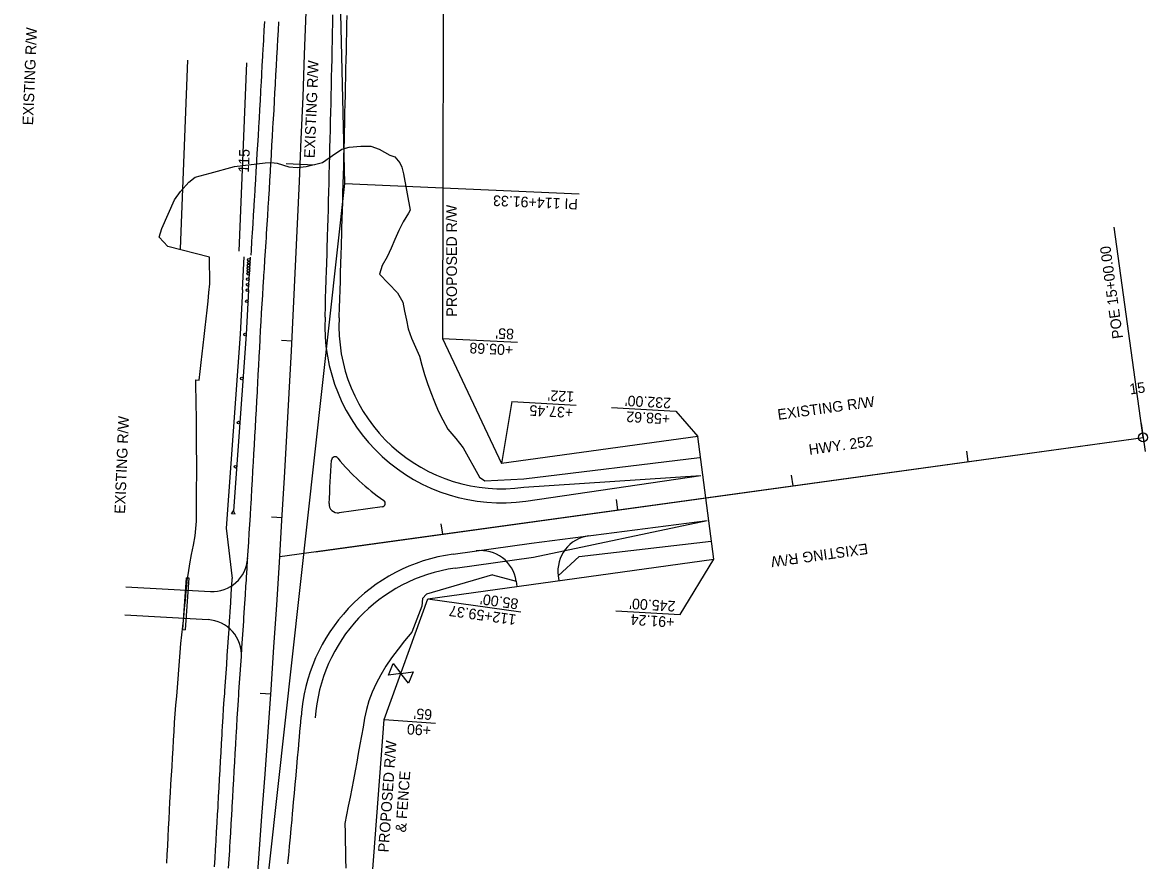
# Model space of a CAD drawing. Extents: x 634057 to 641016, y 287858 to 292331.
# Drawn here: x 634159 to 634795, y 289971 to 290445 of the extents above; entities that cross this region are included whole.
import ezdxf

# ---------------------------------------------------------------- set-up
doc = ezdxf.new("R2010")
doc.units = 0
for name, color, linetype in [('53', 7, 'Continuous'), ('B_Concrete', 7, 'Continuous'), ('R_50 Horz Alg PC PI PT', 7, 'Continuous'), ('R_50 Horz Alg Stations', 7, 'Continuous'), ('R_50 Horz Alg Ticks', 7, 'Continuous'), ('R_Draft', 7, 'Continuous'), ('R_Drive', 7, 'Continuous'), ('R_Horz Alg', 7, 'Continuous'), ('R_No Plot', 7, 'Continuous'), ('R_Proposed Const Limits', 7, 'Continuous'), ('R_Proposed Road', 7, 'Continuous'), ('R_Proposed Shoulder', 7, 'Continuous'), ('R_ROW', 7, 'Continuous'), ('R_Water', 7, 'Continuous'), ('S_BRIDGE', 7, 'Continuous')]:
    doc.layers.add(name, color=color, linetype=linetype)

msp = doc.modelspace()

# ---------------------------------------------------------------- linework, layer by layer
at = {"layer": '53'}
for p, q in [((634396.26, 290266.17), (634438.58, 290264.11)), ((634435.44, 290230.58), (634429.51, 290195.43)), ((634435.44, 290230.58), (634471.74, 290228.52)), ((634491.77, 290227.08), (634528.08, 290225.02)), ((634528.08, 290225.02), (634540.53, 290210.77)), ((634530.56, 290110.13), (634549.54, 290141.35)), ((634387.84, 290119.01), (634440.59, 290111.66)), ((634494.25, 290112.19), (634530.56, 290110.13)), ((634363.24, 290050.68), (634392.24, 290048.66))]:
    msp.add_line(p, q, dxfattribs=at)
at = {"layer": 'B_Concrete'}
msp.add_line((634362.13, 290170.98), (634337.71, 290167.61), dxfattribs=at)
for centre, radius, start, end in [((622866.97, 290851.82), 11485.16, 356.61091, 356.733292), ((634335.46, 290197.24), 2, 38.87832, 176.73329), ((634429.65, 290273.18), 119, 218.87832, 235.9205), ((634337.03, 290172.56), 5, 176.61091, 277.86423), ((634361.85, 290172.96), 2, 277.86423, 55.9205)]:
    msp.add_arc(centre, radius, start, end, dxfattribs=at)
at = {"layer": 'R_50 Horz Alg PC PI PT'}
for points in [[(634341.05, 290353.77), (634322.94, 291121.85)], [(634256.46, 289590.15), (634341.05, 290353.77)], [(634341.05, 290353.77), (634473.54, 290348.02)], [(634792.34, 290210.22), (634775.93, 290329.09)]]:
    msp.add_lwpolyline(points, dxfattribs=at)
msp.add_circle((634792.34, 290210.22), 2.5, dxfattribs=at)
at = {"layer": 'R_50 Horz Alg Ticks'}
for points in [[(634307.77, 290365.04), (634323.76, 290364.36)], [(634305.09, 290265.12), (634311.08, 290264.81)], [(634791.25, 290218.14), (634793.44, 290202.29)], [(634692.46, 290202.48), (634693.28, 290196.54)], [(634593.4, 290188.8), (634594.23, 290182.85)], [(634494.34, 290175.11), (634495.17, 290169.17)], [(634299.53, 290165.32), (634305.52, 290164.96)], [(634395.29, 290161.43), (634396.11, 290155.49)], [(634293.1, 290065.58), (634299.09, 290065.17)]]:
    msp.add_lwpolyline(points, dxfattribs=at)
at = {"layer": 'R_Draft'}
for p, q in [((634283.1, 290293.57), (634284.08, 290312.29)), ((634286.59, 290293.39), (634287.58, 290312.11)), ((634283.1, 290293.57), (634281.79, 290268.6)), ((634286.59, 290293.39), (634285.28, 290268.42)), ((634281.79, 290268.67), (634273.82, 290158.88)), ((634285.28, 290268.42), (634278.04, 290168.67)), ((634276.92, 290167.02), (634278.04, 290168.67)), ((634278.91, 290166.87), (634276.92, 290167.02)), ((634278.91, 290166.87), (634278.04, 290168.67)), ((634273.82, 290158.88), (634277.34, 290130.36))]:
    msp.add_line(p, q, dxfattribs=at)
for centre in [(634286.75, 290310.59), (634286.42, 290304.35), (634286.5, 290305.91), (634286.58, 290307.47), (634286.66, 290309.03), (634286.17, 290299.67), (634286.34, 290302.79), (634285.85, 290293.43), (634286.01, 290296.55), (634285.52, 290287.18), (634284.53, 290268.44), (634282.72, 290243.51), (634280.91, 290218.57), (634279.1, 290193.64)]:
    msp.add_circle(centre, 0.75, dxfattribs=at)
at = {"layer": 'R_Drive'}
for p, q in [((634217.23, 290125.81), (634264.99, 290123.13)), ((634437.82, 290128.95), (634438.23, 290125.97)), ((634461.63, 290131.95), (634462.01, 290129.26)), ((634216.58, 290109.83), (634263.62, 290107.18))]:
    msp.add_line(p, q, dxfattribs=at)
for centre, start, end in [((634481.45, 290134.69), 97.37406, 187.86423), ((634418.01, 290126.21), 7.86423, 97.86423), ((634266.11, 290143.1), 266.78441, 356.44232), ((634262.5, 290087.21), 356.16138, 86.78441)]:
    msp.add_arc(centre, 20, start, end, dxfattribs=at)
at = {"layer": 'R_Horz Alg'}
for p in [(634304.17, 290142.79), (634324.38, 290145.58)]:
    msp.add_line(p, (634792.34, 290210.22), dxfattribs=at)
msp.add_arc((622866.97, 290851.82), 11459.16, 353.678846, 1.350269, dxfattribs=at)
at = {"layer": 'R_Proposed Const Limits'}
for points in [[(634237.45, 290328.26), (634244.72, 290344.5), (634248.03, 290349.21), (634252.79, 290354.51), (634256.39, 290357.36), (634264.74, 290359.69), (634278.5, 290363.4), (634295.95, 290365.51), (634299.34, 290365.72), (634302.72, 290365.2), (634309.39, 290363.29), (634313.94, 290362.87), (634319.12, 290363.4), (634328.32, 290365.72), (634333.93, 290369.64), (634339.32, 290373.24), (634343.45, 290374.4), (634350.11, 290374.93), (634355.72, 290374.83), (634360.38, 290373.24), (634366.41, 290369.85), (634369.26, 290368.9), (634372.01, 290365.51), (634373.18, 290362.97), (634374.23, 290359.27), (634377.9, 290338.77)], [(634377.9, 290338.77), (634376.9, 290336.94), (634373.95, 290332.04), (634371.51, 290327.12), (634369.34, 290322.19), (634367.15, 290317.26), (634364.97, 290312.34), (634362.05, 290307.45), (634360.62, 290302.49), (634365.72, 290297.21), (634370.81, 290291.94), (634373.78, 290286.76), (634374.79, 290281.68), (634375.81, 290276.59), (634376.86, 290271.51), (634378.64, 290266.38), (634380.98, 290261.22), (634383.17, 290256.07), (634384.43, 290250.97), (634386, 290245.85), (634387.64, 290240.72), (634389.59, 290235.58), (634389.6, 290235.57), (634391.59, 290230.42), (634393.74, 290225.26), (634396.32, 290220.08), (634399.25, 290214.87)], [(634244.68, 290048.96), (634245.04, 290053.93), (634245.47, 290058.88), (634245.9, 290063.84), (634246.32, 290068.8), (634246.73, 290073.76), (634247.14, 290078.72), (634247.54, 290083.69), (634247.93, 290088.65), (634248.32, 290093.61), (634248.84, 290098.56), (634249.37, 290103.52), (634249.89, 290108.47), (634250.36, 290113.43), (634250.83, 290118.38), (634251.3, 290123.34), (634251.75, 290128.3), (634251.71, 290128.33), (634252.56, 290133.57), (634253.42, 290138.81), (634254.36, 290144.07), (634255.33, 290149.32), (634256.3, 290154.58), (634257.09, 290162.88), (634257.1, 290167.87), (634257.12, 290172.86), (634257.15, 290177.84), (634257.17, 290182.83), (634257.2, 290187.82), (634257.23, 290192.8), (634257.22, 290197.79), (634257.19, 290202.78), (634257.16, 290207.76), (634257.14, 290212.75), (634257.12, 290217.74), (634257.08, 290222.72), (634256.98, 290227.71), (634256.89, 290232.7), (634256.79, 290237.69), (634256.7, 290242.68), (634258.61, 290242.59), (634259.17, 290247.53), (634259.74, 290252.49), (634260.31, 290257.44), (634260.86, 290262.4), (634261.41, 290267.36), (634261.99, 290272.31), (634262.54, 290277.27), (634263.09, 290282.23), (634263.63, 290287.18), (634264.16, 290292.14), (634264.58, 290297.11), (634264.56, 290302.09), (634264.53, 290307.08), (634264.53, 290312.06), (634240.89, 290318.16), (634236.08, 290323.35), (634237.45, 290328.26)], [(634399.25, 290214.87), (634403.83, 290209.57), (634407.85, 290204.29), (634417.05, 290187.81)], [(634417.05, 290187.81), (634420.12, 290185.73), (634442.13, 290186.82), (634541.53, 290198.9)], [(634461.63, 290131.95), (634473.46, 290142.94), (634548.08, 290151.47)], [(634424.51, 290132.54), (634387.21, 290121.49), (634384.83, 290119.14), (634384.55, 290114.82)], [(634424.51, 290132.54), (634437.82, 290128.95)], [(634384.55, 290114.82), (634378.77, 290100.05), (634374.78, 290095.27), (634371.08, 290090.47), (634367.45, 290085.67), (634364.18, 290080.85), (634361.27, 290076.01), (634358.68, 290071.15), (634356.4, 290066.26), (634354.58, 290061.35), (634353.19, 290056.41), (634352.15, 290051.45), (634351.32, 290046.47), (634350.43, 290041.5), (634349.5, 290036.53), (634348.59, 290031.56), (634347.68, 290026.59), (634346.77, 290021.62), (634345.9, 290016.65), (634344.95, 290011.68), (634343.95, 290006.72), (634342.95, 290001.76), (634341.96, 289996.8), (634341.07, 289991.83), (634341.1, 289986.79), (634341.19, 289981.75), (634341.32, 289976.7), (634341.43, 289971.66), (634341.54, 289966.62)], [(634240.28, 289969.43), (634240.55, 289974.41), (634240.82, 289979.38), (634241.07, 289984.35), (634241.32, 289989.32), (634241.57, 289994.3), (634241.8, 289999.27), (634242.03, 290004.24), (634242.35, 290009.21), (634242.66, 290014.18), (634242.97, 290019.15), (634243.27, 290024.11), (634243.55, 290029.08), (634243.84, 290034.05), (634244.12, 290039.02), (634244.39, 290043.99), (634244.68, 290048.96)]]:
    msp.add_lwpolyline(points, dxfattribs=at)
at = {"layer": 'R_Proposed Road'}
for p, q in [((634443.34, 290174.12), (634542.27, 290188.7)), ((634446.62, 290150.35), (634545.8, 290163.19)), ((634402.3, 290144.23), (634446.62, 290150.35))]:
    msp.add_line(p, q, dxfattribs=at)
for points in [[(634275.26, 289966.72), (634275.56, 289971.71), (634275.86, 289976.69), (634275.98, 289978.69), (634276.16, 289981.67), (634276.45, 289986.66), (634276.74, 289991.64), (634277.04, 289996.63), (634277.25, 290000.24), (634277.32, 290001.61), (634277.61, 290006.6), (634277.9, 290011.58), (634278.18, 290016.57), (634278.46, 290021.55), (634278.47, 290021.78), (634278.74, 290026.54), (634279.01, 290031.52), (634279.29, 290036.51), (634279.56, 290041.5), (634279.66, 290043.33), (634279.83, 290046.48), (634280.09, 290051.47), (634280.44, 290056.45), (634280.79, 290061.43), (634281.03, 290064.86), (634281.13, 290066.41), (634281.47, 290071.39), (634281.81, 290076.37), (634282.15, 290081.35), (634282.49, 290086.33), (634282.49, 290086.39), (634282.82, 290091.31), (634283.15, 290096.29), (634283.48, 290101.27), (634283.8, 290106.25), (634283.91, 290107.92), (634284.13, 290111.24), (634284.45, 290116.22), (634284.77, 290121.2), (634285.09, 290126.18), (634285.3, 290129.45), (634285.4, 290131.16), (634285.72, 290136.15), (634286.03, 290141.13), (634286.34, 290146.11), (634286.64, 290150.98), (634286.64, 290151.09), (634286.95, 290156.08), (634287.25, 290161.06), (634287.55, 290166.04), (634287.85, 290171.03), (634287.94, 290172.52), (634288.15, 290176.01), (634288.44, 290180.99), (634288.73, 290185.98), (634289.02, 290190.96), (634289.2, 290194.06), (634289.31, 290195.94), (634289.59, 290200.93), (634289.88, 290205.91), (634290.16, 290210.9), (634290.42, 290215.6), (634290.44, 290215.88), (634290.71, 290220.87), (634290.99, 290225.85), (634291.26, 290230.84), (634291.53, 290235.82), (634291.6, 290237.14), (634291.8, 290240.8), (634292.06, 290245.79), (634292.32, 290250.78), (634292.59, 290255.76), (634292.74, 290258.69), (634292.84, 290260.75), (634293.1, 290265.73), (634293.36, 290270.72), (634293.61, 290275.7), (634293.84, 290280.24), (634293.86, 290280.69), (634294.19, 290285.67), (634294.52, 290290.65), (634294.85, 290295.63), (634295.17, 290300.62), (634295.25, 290301.77), (634295.49, 290305.6), (634295.81, 290310.58), (634296.13, 290315.57), (634296.45, 290320.55), (634296.62, 290323.3), (634296.76, 290325.53), (634297.07, 290330.52), (634297.38, 290335.5), (634297.69, 290340.48), (634297.96, 290344.84), (634298, 290345.47), (634298.3, 290350.45), (634298.6, 290355.44), (634298.9, 290360.42), (634299.2, 290365.4), (634299.25, 290366.38), (634299.49, 290370.39), (634299.78, 290375.37), (634300.07, 290380.36), (634300.36, 290385.34), (634300.51, 290387.93), (634300.65, 290390.33), (634300.93, 290395.32), (634301.21, 290400.3), (634301.49, 290405.29), (634301.72, 290409.48), (634301.77, 290410.27), (634302.04, 290415.26), (634302.32, 290420.25), (634302.59, 290425.23), (634302.85, 290430.22), (634302.9, 290431.03), (634303.12, 290435.21), (634303.38, 290440.19), (634303.65, 290445.18)], [(634329.78, 290278.18), (634329.79, 290278.44), (634329.81, 290278.89), (634329.98, 290283.9), (634330.14, 290288.9), (634330.3, 290293.91), (634330.46, 290298.91), (634330.5, 290300.07), (634330.62, 290303.92), (634330.78, 290308.93), (634330.93, 290313.93), (634331.08, 290318.94), (634331.16, 290321.71), (634331.23, 290323.94), (634331.37, 290328.95), (634331.52, 290333.96), (634331.66, 290338.96), (634331.78, 290343.34), (634331.8, 290343.97), (634331.93, 290348.98), (634332.07, 290353.98), (634332.2, 290358.99), (634332.33, 290363.99), (634332.36, 290364.98), (634332.46, 290369), (634332.59, 290374.01), (634332.71, 290379.01), (634332.83, 290384.02), (634332.9, 290386.62), (634332.95, 290389.03), (634333.07, 290394.03), (634333.19, 290399.04), (634333.3, 290404.04), (634333.39, 290408.25), (634333.41, 290409.05), (634333.52, 290414.06), (634333.63, 290419.06), (634333.73, 290424.07), (634333.83, 290429.08), (634333.85, 290429.89), (634333.93, 290434.08), (634334.03, 290439.09), (634334.13, 290444.1), (634334.22, 290449.1)], [(634308.79, 289969.14), (634309.26, 289974.13), (634309.45, 289976.13), (634309.73, 289979.11), (634310.19, 289984.1), (634310.65, 289989.09), (634311.11, 289994.07), (634311.44, 289997.69), (634311.56, 289999.06), (634312.02, 290004.05), (634312.47, 290009.04), (634312.92, 290014.03), (634313.37, 290019.01), (634313.39, 290019.24), (634313.81, 290024), (634314.26, 290028.99), (634314.7, 290033.98), (634315.14, 290038.97), (634315.3, 290040.8), (634315.57, 290043.96), (634316.01, 290048.95), (634316.23, 290052.14)]]:
    msp.add_lwpolyline(points, dxfattribs=at)
for centre, start, end in [((634429.65, 290273.18), 177.13512, 277.86423), ((634415.99, 290045.17), 97.86423, 176.00462)]:
    msp.add_arc(centre, 100, start, end, dxfattribs=at)
at = {"layer": 'R_Proposed Shoulder'}
for p, q in [((634442.24, 290182.05), (634542.27, 290188.7)), ((634447.71, 290142.43), (634545.8, 290163.19)), ((634403.4, 290136.3), (634447.71, 290142.43))]:
    msp.add_line(p, q, dxfattribs=at)
for points in [[(634287.97, 290313.24), (634288.14, 290315.94), (634288.46, 290320.92), (634288.63, 290323.67), (634288.77, 290325.9), (634289.08, 290330.88), (634289.39, 290335.86), (634289.7, 290340.84), (634289.97, 290345.2), (634290, 290345.82), (634290.31, 290350.8), (634290.61, 290355.78), (634290.91, 290360.76), (634291.2, 290365.74), (634291.26, 290366.72), (634291.5, 290370.73), (634291.79, 290375.71), (634292.08, 290380.69), (634292.37, 290385.67), (634292.52, 290388.25), (634292.65, 290390.65), (634292.94, 290395.63), (634293.22, 290400.62), (634293.5, 290405.6), (634293.73, 290409.79), (634293.77, 290410.58), (634294.05, 290415.56), (634294.32, 290420.55), (634294.59, 290425.53), (634294.86, 290430.51), (634294.9, 290431.32), (634295.13, 290435.5), (634295.39, 290440.48), (634295.65, 290445.46)], [(634337.77, 290277.78), (634337.78, 290278.04), (634337.8, 290278.49), (634337.97, 290283.5), (634338.13, 290288.51), (634338.29, 290293.52), (634338.45, 290298.53), (634338.49, 290299.69), (634338.61, 290303.54), (634338.77, 290308.55), (634338.92, 290313.56), (634339.07, 290318.57), (634339.15, 290321.34), (634339.22, 290323.58), (634339.36, 290328.59), (634339.51, 290333.6), (634339.65, 290338.61), (634339.77, 290342.99), (634339.79, 290343.62), (634339.93, 290348.63), (634340.06, 290353.63), (634340.19, 290358.64), (634340.33, 290363.65), (634340.35, 290364.64), (634340.45, 290368.66), (634340.58, 290373.67), (634340.71, 290378.68), (634340.83, 290383.69), (634340.89, 290386.29), (634340.95, 290388.7), (634341.06, 290393.71), (634341.18, 290398.72), (634341.29, 290403.73), (634341.39, 290407.94), (634341.4, 290408.74), (634341.51, 290413.75), (634341.62, 290418.76), (634341.73, 290423.77), (634341.83, 290428.78), (634341.84, 290429.6), (634341.93, 290433.79), (634342.03, 290438.8), (634342.12, 290443.81), (634342.22, 290448.82)], [(634267.28, 289967.34), (634267.58, 289972.32), (634267.88, 289977.3), (634268, 289979.3), (634268.18, 289982.28), (634268.47, 289987.26), (634268.77, 289992.25), (634269.06, 289997.23), (634269.27, 290000.83), (634269.35, 290002.21), (634269.63, 290007.19), (634269.92, 290012.17), (634270.2, 290017.15), (634270.48, 290022.13), (634270.49, 290022.36), (634270.76, 290027.12), (634271.03, 290032.1), (634271.31, 290037.08), (634271.58, 290042.06), (634271.68, 290043.89), (634271.85, 290047.04), (634272.11, 290052.03), (634272.46, 290057), (634272.81, 290061.98), (634273.05, 290065.41), (634273.15, 290066.96), (634273.49, 290071.93), (634273.83, 290076.91), (634274.17, 290081.89), (634274.5, 290086.87), (634274.51, 290086.92), (634274.84, 290091.84), (634275.17, 290096.82), (634275.5, 290101.8), (634275.82, 290106.78), (634275.93, 290108.44), (634276.15, 290111.75), (634276.47, 290116.73), (634276.79, 290121.71), (634277.1, 290126.69), (634277.31, 290129.95), (634277.34, 290130.36)]]:
    msp.add_lwpolyline(points, dxfattribs=at)
for centre, start, end in [((634429.65, 290273.18), 177.13512, 277.86423), ((634415.99, 290045.17), 97.86423, 176.00462)]:
    msp.add_arc(centre, 92, start, end, dxfattribs=at)
at = {"layer": 'R_ROW'}
for p, q in [((634365.6, 290075.79), (634368.24, 290082.34)), ((634368.24, 290082.34), (634372.6, 290076.77)), ((634372.6, 290076.77), (634365.6, 290075.79)), ((634372.6, 290076.77), (634379.6, 290077.76)), ((634376.95, 290071.21), (634372.6, 290076.77)), ((634379.6, 290077.76), (634376.95, 290071.21))]:
    msp.add_line(p, q, dxfattribs=at)
for points in [[(634385.92, 290784.2), (634396.7, 290532.52), (634396.26, 290266.17), (634429.51, 290195.43)], [(634387.84, 290119.01), (634549.54, 290141.35), (634540.53, 290210.77), (634429.51, 290195.43)], [(634363.24, 290050.68), (634387.84, 290119.01)], [(634329.31, 289374.55), (634319.38, 289660.99), (634353.08, 289916.2), (634363.24, 290050.68)]]:
    msp.add_lwpolyline(points, dxfattribs=at)
at = {"layer": 'R_Water'}
for points in [[(634251.33, 290130.84), (634249.26, 290101.52)], [(634252.83, 290130.73), (634250.76, 290101.42)], [(634251.33, 290130.84), (634252.83, 290130.73)], [(634249.26, 290101.52), (634250.76, 290101.42)]]:
    msp.add_lwpolyline(points, dxfattribs=at)
at = {"layer": 'S_BRIDGE'}
for p, q in [((634247.98, 290316.77), (634252.22, 290423.52)), ((634285.44, 290422.04), (634281.09, 290315.6))]:
    msp.add_line(p, q, dxfattribs=at)

# ---------------------------------------------------------------- texts
at = {"layer": '53'}
for s, rotation, p in [('EXISTING R/W', 87.69322, (634164.68, 290386.63)), ('EXISTING R/W', 87.69322, (634323.92, 290368.02)), ('PROPOSED R/W', 90.13185, (634404.44, 290278.45)), ("85'  ", 177.21366, (634436.75, 290271.57)), ('+05.68 ', 177.21366, (634436.32, 290262.58)), ("122'  ", 176.7509, (634470.76, 290236.11)), ("232.00'  ", 176.85677, (634525.57, 290232.55)), ('+37.45 ', 176.7509, (634470.25, 290227.12)), ('EXISTING R/W', 7.86423, (634586.08, 290220.09)), ('EXISTING R/W', 87.69322, (634216.68, 290166.91)), ('+58.62 ', 176.85677, (634525.07, 290223.57)), ('EXISTING R/W', 187.86423, (634636.32, 290150.31)), ("85.00'  ", 172.06931, (634439.4, 290118.87)), ('112+59.37 ', 172.06931, (634438.16, 290109.96)), ("245.00'  ", 176.51986, (634528.06, 290117.66)), ('+91.24 ', 176.51986, (634527.52, 290108.68)), ("65'  ", 176.01366, (634390.54, 290056.37)), ('+90 ', 176.01366, (634389.92, 290047.39)), ('PROPOSED R/W', 85.92206, (634365.71, 289975.43)), ('& FENCE', 85.92206, (634375.54, 289986.75))]:
    msp.add_text(s, height=6, rotation=rotation, dxfattribs=at).set_placement(p)
at = {"layer": 'R_50 Horz Alg PC PI PT'}
for s, rotation, p in [('PI 114+91.33', 177.51456, (634472.85, 290345.02)), ('POE 15+00.00', 97.86423, (634781.05, 290266.41))]:
    msp.add_text(s, height=6, rotation=rotation, dxfattribs=at).set_placement(p)
at = {"layer": 'R_50 Horz Alg Stations'}
for s, rotation, p in [('115', 87.56366, (634286.69, 290359.77)), ('15', 7.86423, (634785.05, 290234.45)), ('HWY. 252', 7.86423, (634603.73, 290200.3))]:
    msp.add_text(s, height=6, rotation=rotation, dxfattribs=at).set_placement(p)
at = {"layer": 'R_No Plot'}
for rotation, p in [(87.39101, (634314.29, 290330.16)), (87.18566, (634294.64, 290295.6)), (87.18566, (634294.64, 290295.6)), (7.86423, (634792.31, 290210.16)), (7.86423, (634792.31, 290210.16)), (7.86423, (634304.13, 290142.73)), (86.01667, (634280.14, 290051.42)), (86.01667, (634280.14, 290051.42)), (86.01667, (634280.14, 290051.42))]:
    msp.add_text('+', height=0.1, rotation=rotation, dxfattribs=at).set_placement(p)

doc.saveas('drawing.dxf')
